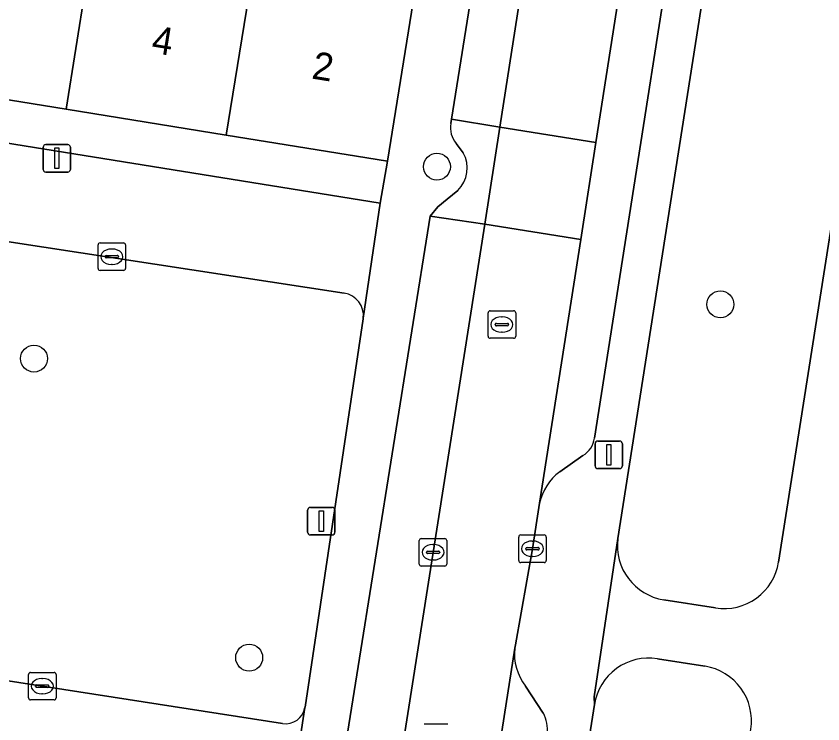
# Model space of a CAD drawing. Extents: x 163008 to 163854, y 382777 to 383982.
# Drawn here: x 163253.69 to 163282.98, y 383111.73 to 383137.42 of the extents above; entities that cross this region are included whole.
import ezdxf

# ---------------------------------------------------------------- set-up
doc = ezdxf.new("R2010")
doc.units = 0
for name, color, linetype in [('IMGEO_Boom', 7, 'Continuous'), ('IMGEO_Erf', 7, 'Continuous'), ('IMGEO_Groenvoorziening', 7, 'Continuous'), ('IMGEO_Kolk', 7, 'Continuous'), ('IMGEO_Lichtmast', 7, 'Continuous'), ('IMGEO_Pand', 7, 'Continuous'), ('IMGEO_Pand_nummerreeks', 7, 'Continuous'), ('IMGEO_Parkeervlak_open', 7, 'Continuous'), ('IMGEO_Rijbaan_lokaal_open', 7, 'Continuous'), ('IMGEO_Rioolput', 7, 'Continuous'), ('IMGEO_Verkeersbordpaal', 7, 'Continuous'), ('IMGEO_Voetpad_open', 7, 'Continuous')]:
    doc.layers.add(name, color=color, linetype=linetype)

msp = doc.modelspace()

# ---------------------------------------------------------------- linework, layer by layer
at = {"layer": 'IMGEO_Boom'}
for centre in [(163268.964, 383131.957), (163279.255, 383126.958), (163254.337, 383124.992), (163262.149, 383114.131)]:
    msp.add_circle(centre, 0.489, dxfattribs=at)
at = {"layer": 'IMGEO_Erf'}
msp.add_lwpolyline([(163255.5, 383134.044), (163249.739, 383134.974), (163243.979, 383135.904), (163238.071, 383136.858), (163237.896, 383135.882), (163237.819, 383135.321), (163266.909, 383130.633), (163267.168, 383132.16), (163261.316, 383133.105)], close=True, dxfattribs=at)
at = {"layer": 'IMGEO_Groenvoorziening'}
for points in [[(163285.801, 383145.855), (163279.973, 383146.774), (163275.529, 383118.456)], [(163281.366, 383117.602), (163285.801, 383145.855)], [(163265.602, 383127.364), (163239.589, 383131.347), (163239.155, 383130.7), (163236.864, 383116.463)], [(163264.173, 383112.32), (163264.176, 383112.34), (163266.288, 383126.43), (163266.291, 383126.455)], [(163277.202, 383116.233), (163279.079, 383115.937)], [(163237.36, 383115.781), (163263.363, 383111.743)], [(163278.696, 383113.82), (163276.967, 383114.093)], [(163274.68, 383112.429), (163270.193, 383083.981), (163275.873, 383083.085), (163280.36, 383111.533)]]:
    msp.add_lwpolyline(points, dxfattribs=at)
for centre, radius, start, end in [((163265.473, 383126.551), 0.823, 353.3139, 81.0086), ((163277.514, 383118.208), 2, 172.8902, 261.0391), ((163279.391, 383117.912), 1.999, 261.0219, 351.0895), ((163276.655, 383112.118), 1.999, 81.025, 171.0536), ((163278.387, 383111.846), 1.998, 350.9843, 81.0943), ((163263.472, 383112.447), 0.712, 261.1914, 349.7366)]:
    msp.add_arc(centre, radius, start, end, dxfattribs=at)
at = {"layer": 'IMGEO_Kolk'}
for p, q in [((163256.661, 383128.263), (163256.661, 383129.115)), ((163256.736, 383129.189), (163257.588, 383129.189)), ((163257.662, 383129.115), (163257.662, 383128.263)), ((163257.149, 383128.969), (163257.174, 383128.969)), ((163256.92, 383128.683), (163256.92, 383128.695)), ((163257.358, 383128.646), (163256.96, 383128.646)), ((163256.963, 383128.732), (163257.361, 383128.732)), ((163257.404, 383128.695), (163257.404, 383128.683)), ((163257.172, 383128.409), (163257.147, 383128.409)), ((163257.588, 383128.189), (163256.736, 383128.189)), ((163272.008, 383118.586), (163272.86, 383118.586)), ((163268.323, 383117.532), (163268.323, 383118.384)), ((163268.398, 383118.458), (163269.25, 383118.458)), ((163269.324, 383118.384), (163269.324, 383117.532)), ((163271.933, 383117.66), (163271.933, 383118.512)), ((163272.421, 383118.366), (163272.446, 383118.366)), ((163272.934, 383118.512), (163272.934, 383117.66)), ((163268.625, 383118.001), (163269.023, 383118.001)), ((163268.811, 383118.238), (163268.836, 383118.238)), ((163272.192, 383118.08), (163272.192, 383118.092)), ((163272.63, 383118.043), (163272.232, 383118.043)), ((163272.235, 383118.129), (163272.633, 383118.129)), ((163272.676, 383118.092), (163272.676, 383118.08)), ((163268.582, 383117.952), (163268.582, 383117.964)), ((163269.02, 383117.915), (163268.622, 383117.915)), ((163269.066, 383117.964), (163269.066, 383117.952)), ((163272.444, 383117.806), (163272.419, 383117.806)), ((163269.25, 383117.458), (163268.398, 383117.458)), ((163268.834, 383117.678), (163268.809, 383117.678)), ((163272.86, 383117.586), (163272.008, 383117.586)), ((163254.214, 383113.597), (163255.066, 383113.597)), ((163254.139, 383112.671), (163254.139, 383113.523)), ((163254.627, 383113.377), (163254.652, 383113.377)), ((163255.14, 383113.523), (163255.14, 383112.671)), ((163254.398, 383113.091), (163254.398, 383113.103)), ((163254.836, 383113.054), (163254.438, 383113.054)), ((163254.441, 383113.14), (163254.839, 383113.14)), ((163254.882, 383113.103), (163254.882, 383113.091)), ((163254.65, 383112.817), (163254.625, 383112.817)), ((163255.066, 383112.597), (163254.214, 383112.597))]:
    msp.add_line(p, q, dxfattribs=at)
for points in [[(163256.661, 383128.263), (163256.661, 383129.115)], [(163256.736, 383129.189), (163257.588, 383129.189)], [(163257.662, 383129.115), (163257.662, 383128.263)], [(163257.588, 383128.189), (163256.736, 383128.189)], [(163272.008, 383118.586), (163272.86, 383118.586)], [(163268.323, 383117.532), (163268.323, 383118.384)], [(163268.398, 383118.458), (163269.25, 383118.458)], [(163269.324, 383118.384), (163269.324, 383117.532)], [(163271.933, 383117.66), (163271.933, 383118.512)], [(163272.934, 383118.512), (163272.934, 383117.66)], [(163269.25, 383117.458), (163268.398, 383117.458)], [(163272.86, 383117.586), (163272.008, 383117.586)], [(163254.214, 383113.597), (163255.066, 383113.597)], [(163254.139, 383112.671), (163254.139, 383113.523)], [(163255.14, 383113.523), (163255.14, 383112.671)], [(163255.066, 383112.597), (163254.214, 383112.597)]]:
    msp.add_lwpolyline(points, dxfattribs=at)
for centre, radius, start, end in [((163256.738, 383129.113), 0.0765, 91.552, 178.448), ((163256.738, 383129.113), 0.0765, 91.552, 178.448), ((163257.586, 383129.113), 0.0765, 1.552, 88.448), ((163257.586, 383129.113), 0.0765, 1.552, 88.448), ((163256.96, 383128.692), 0.0403, 85.8775, 175.7526), ((163256.957, 383128.682), 0.0366, 178.938, 274.7102), ((163257.361, 383128.689), 0.043, 264.8664, 352.4533), ((163257.365, 383128.694), 0.0386, 1.7309, 96.639), ((163256.738, 383128.265), 0.0765, 181.552, 268.448), ((163256.738, 383128.265), 0.0765, 181.552, 268.448), ((163257.586, 383128.265), 0.0765, 271.552, 358.448), ((163257.586, 383128.265), 0.0765, 271.552, 358.448), ((163272.01, 383118.51), 0.0765, 91.552, 178.448), ((163272.01, 383118.51), 0.0765, 91.552, 178.448), ((163272.858, 383118.51), 0.0765, 1.552, 88.448), ((163272.858, 383118.51), 0.0765, 1.552, 88.448), ((163268.4, 383118.382), 0.0765, 91.552, 178.448), ((163268.4, 383118.382), 0.0765, 91.552, 178.448), ((163269.248, 383118.382), 0.0765, 1.552, 88.448), ((163269.248, 383118.382), 0.0765, 1.552, 88.448), ((163268.622, 383117.961), 0.0403, 85.8775, 175.7526), ((163269.027, 383117.963), 0.0386, 1.7309, 96.639), ((163272.232, 383118.089), 0.0403, 85.8775, 175.7526), ((163272.229, 383118.079), 0.0366, 178.938, 274.7102), ((163272.633, 383118.086), 0.043, 264.8664, 352.4533), ((163272.637, 383118.091), 0.0386, 1.7309, 96.639), ((163268.619, 383117.951), 0.0366, 178.938, 274.7102), ((163269.023, 383117.958), 0.043, 264.8664, 352.4533), ((163268.4, 383117.534), 0.0765, 181.552, 268.448), ((163268.4, 383117.534), 0.0765, 181.552, 268.448), ((163269.248, 383117.534), 0.0765, 271.552, 358.448), ((163269.248, 383117.534), 0.0765, 271.552, 358.448), ((163272.01, 383117.662), 0.0765, 181.552, 268.448), ((163272.01, 383117.662), 0.0765, 181.552, 268.448), ((163272.858, 383117.662), 0.0765, 271.552, 358.448), ((163272.858, 383117.662), 0.0765, 271.552, 358.448), ((163254.216, 383113.521), 0.0765, 91.552, 178.448), ((163254.216, 383113.521), 0.0765, 91.552, 178.448), ((163255.064, 383113.521), 0.0765, 1.552, 88.448), ((163255.064, 383113.521), 0.0765, 1.552, 88.448), ((163254.438, 383113.1), 0.0403, 85.8775, 175.7526), ((163254.435, 383113.09), 0.0366, 178.938, 274.7102), ((163254.839, 383113.097), 0.043, 264.8664, 352.4533), ((163254.843, 383113.102), 0.0386, 1.7309, 96.639), ((163254.216, 383112.673), 0.0765, 181.552, 268.448), ((163254.216, 383112.673), 0.0765, 181.552, 268.448), ((163255.064, 383112.673), 0.0765, 271.552, 358.448), ((163255.064, 383112.673), 0.0765, 271.552, 358.448)]:
    msp.add_arc(centre, radius, start, end, dxfattribs=at)
for centre, major_axis, ratio, start_param, end_param in [((163257.148, 383128.689), (-0.387, 0.002), 0.722429, 4.712389, 7.853982), ((163257.173, 383128.689), (-0.39, 0.002), 0.717154, 1.570796, 4.712389), ((163272.42, 383118.086), (-0.387, 0.002), 0.722429, 4.712389, 7.853982), ((163272.445, 383118.086), (-0.39, 0.002), 0.717154, 1.570796, 4.712389), ((163268.81, 383117.958), (-0.387, 0.002), 0.722429, 4.712389, 7.853982), ((163268.835, 383117.958), (-0.39, 0.002), 0.717154, 1.570796, 4.712389), ((163254.626, 383113.097), (-0.387, 0.002), 0.722429, 4.712389, 7.853982), ((163254.651, 383113.097), (-0.39, 0.002), 0.717154, 1.570796, 4.712389)]:
    msp.add_ellipse(centre, major_axis=major_axis, ratio=ratio, start_param=start_param, end_param=end_param, dxfattribs=at)
at = {"layer": 'IMGEO_Lichtmast'}
for p, q in [((163254.67, 383131.861), (163254.67, 383132.661)), ((163254.67, 383132.661), (163254.67, 383131.861)), ((163254.77, 383132.761), (163255.56, 383132.761)), ((163255.56, 383132.761), (163254.77, 383132.761)), ((163255.66, 383132.661), (163255.66, 383131.861)), ((163255.66, 383131.861), (163255.66, 383132.661)), ((163255.56, 383131.761), (163254.77, 383131.761)), ((163254.77, 383131.761), (163255.56, 383131.761)), ((163274.707, 383121.097), (163274.707, 383121.897)), ((163274.707, 383121.897), (163274.707, 383121.097)), ((163274.807, 383121.997), (163275.597, 383121.997)), ((163275.597, 383121.997), (163274.807, 383121.997)), ((163275.697, 383121.897), (163275.697, 383121.097)), ((163275.697, 383121.097), (163275.697, 383121.897)), ((163275.597, 383120.997), (163274.807, 383120.997)), ((163274.807, 383120.997), (163275.597, 383120.997))]:
    msp.add_line(p, q, dxfattribs=at)
for points in [[(163255.09, 383132.636), (163255.24, 383132.636), (163255.24, 383131.886), (163255.09, 383131.886), (163255.09, 383132.636)], [(163275.127, 383121.872), (163275.277, 383121.872), (163275.277, 383121.122), (163275.127, 383121.122), (163275.127, 383121.872)]]:
    msp.add_lwpolyline(points, dxfattribs=at)
for centre, start, end in [((163254.77, 383132.661), 90, 180), ((163254.77, 383132.661), 90, 180), ((163255.56, 383132.661), 0, 90), ((163255.56, 383132.661), 360, 90), ((163254.77, 383131.861), 180, 270), ((163254.77, 383131.861), 180, 270), ((163255.56, 383131.861), 270, 0), ((163255.56, 383131.861), 270, 0), ((163274.807, 383121.897), 90, 180), ((163274.807, 383121.897), 90, 180), ((163275.597, 383121.897), 0, 90), ((163275.597, 383121.897), 360, 90), ((163274.807, 383121.097), 180, 270), ((163274.807, 383121.097), 180, 270), ((163275.597, 383121.097), 270, 0), ((163275.597, 383121.097), 270, 0)]:
    msp.add_arc(centre, 0.1, start, end, dxfattribs=at)
at = {"layer": 'IMGEO_Pand'}
for points in [[(163263.102, 383144.124), (163263.872, 383148.876), (163260.267, 383149.442), (163258.74, 383149.682), (163257.974, 383144.953), (163257.264, 383145.068), (163255.5, 383134.044), (163261.316, 383133.105)], [(163255.5, 383134.044), (163257.264, 383145.068), (163251.522, 383145.997), (163251.032, 383142.951), (163249.739, 383134.974)], [(163263.102, 383144.124), (163261.316, 383133.105), (163267.168, 383132.16), (163268.457, 383140.137), (163264.805, 383140.728), (163265.297, 383143.769)]]:
    msp.add_lwpolyline(points, close=True, dxfattribs=at)
at = {"layer": 'IMGEO_Parkeervlak_open'}
for points in [[(163271.119, 383143.834), (163269.499, 383133.678), (163271.253, 383133.395), (163280.323, 383191.611), (163278.747, 383191.863), (163278.555, 383191.425), (163275.791, 383174.012)], [(163281.778, 383177.835), (163274.739, 383132.832), (163274.214, 383129.473), (163274.189, 383129.31), (163272.691, 383119.736)], [(163274.685, 383122.106), (163282.934, 383174.782)], [(163271.253, 383133.395), (163269.499, 383133.678), (163269.474, 383133.523)], [(163269.726, 383131.09), (163269.338, 383130.782), (163268.993, 383130.505), (163268.723, 383130.163), (163270.7, 383129.875), (163271.253, 383133.395)], [(163269.663, 383132.805), (163269.919, 383132.457)], [(163270.7, 383129.875), (163268.723, 383130.163), (163262.069, 383088.528), (163262.063, 383088.302), (163262.115, 383088.172), (163262.782, 383087.359)], [(163259.821, 383060.729), (163270.7, 383129.875)], [(163273.421, 383120.876), (163274.266, 383121.47)], [(163271.794, 383114.476), (163263.513, 383061.443)], [(163272.827, 383112.118), (163272.186, 383113.101)]]:
    msp.add_lwpolyline(points, dxfattribs=at)
for centre, radius, start, end in [((163270.298, 383133.356), 0.841, 168.5587, 220.9363), ((163268.934, 383131.899), 1.132, 314.398, 29.5296), ((163273.822, 383122.218), 0.87, 300.6605, 352.5853), ((163274.552, 383119.348), 1.901, 126.5125, 168.2205), ((163273.609, 383114.25), 1.829, 172.9095, 218.9152), ((163271.635, 383111.501), 1.343, 354.4526, 27.3696)]:
    msp.add_arc(centre, radius, start, end, dxfattribs=at)
at = {"layer": 'IMGEO_Rijbaan_lokaal_open'}
for points in [[(163280.323, 383191.611), (163271.253, 383133.395), (163274.739, 383132.832), (163281.778, 383177.835), (163281.931, 383179.059), (163282.521, 383182.549), (163283.842, 383191.049)], [(163274.739, 383132.832), (163271.253, 383133.395), (163270.7, 383129.875), (163274.189, 383129.31), (163274.214, 383129.473)]]:
    msp.add_lwpolyline(points, close=True, dxfattribs=at)
msp.add_lwpolyline([(163262.832, 383057.207), (163263.513, 383061.443), (163271.794, 383114.476), (163271.812, 383114.593), (163272.433, 383118.086), (163272.691, 383119.736), (163274.189, 383129.31), (163270.7, 383129.875), (163259.821, 383060.729), (163259.673, 383059.48), (163258.688, 383053.576), (163262.311, 383052.831)], dxfattribs=at)
at = {"layer": 'IMGEO_Rioolput'}
for p, q in [((163270.823, 383125.8), (163270.823, 383126.652)), ((163270.898, 383126.726), (163271.75, 383126.726)), ((163271.311, 383126.506), (163271.336, 383126.506)), ((163271.824, 383126.652), (163271.824, 383125.8)), ((163271.082, 383126.22), (163271.082, 383126.232)), ((163271.52, 383126.183), (163271.122, 383126.183)), ((163271.125, 383126.269), (163271.523, 383126.269)), ((163271.566, 383126.232), (163271.566, 383126.22)), ((163271.334, 383125.946), (163271.309, 383125.946)), ((163271.75, 383125.726), (163270.898, 383125.726)), ((163268.506, 383111.728), (163269.358, 383111.728))]:
    msp.add_line(p, q, dxfattribs=at)
for points in [[(163270.823, 383125.8), (163270.823, 383126.652)], [(163270.898, 383126.726), (163271.75, 383126.726)], [(163271.824, 383126.652), (163271.824, 383125.8)], [(163271.75, 383125.726), (163270.898, 383125.726)], [(163268.506, 383111.728), (163269.358, 383111.728)]]:
    msp.add_lwpolyline(points, dxfattribs=at)
for centre, radius, start, end in [((163270.9, 383126.65), 0.0765, 91.552, 178.448), ((163270.9, 383126.65), 0.0765, 91.552, 178.448), ((163271.748, 383126.65), 0.0765, 1.552, 88.448), ((163271.748, 383126.65), 0.0765, 1.552, 88.448), ((163271.122, 383126.229), 0.0403, 85.8775, 175.7526), ((163271.119, 383126.219), 0.0366, 178.938, 274.7102), ((163271.523, 383126.226), 0.043, 264.8664, 352.4533), ((163271.527, 383126.231), 0.0386, 1.7309, 96.639), ((163270.9, 383125.802), 0.0765, 181.552, 268.448), ((163270.9, 383125.802), 0.0765, 181.552, 268.448), ((163271.748, 383125.802), 0.0765, 271.552, 358.448), ((163271.748, 383125.802), 0.0765, 271.552, 358.448)]:
    msp.add_arc(centre, radius, start, end, dxfattribs=at)
for centre, major_axis, ratio, start_param, end_param in [((163271.31, 383126.226), (-0.387, 0.002), 0.722429, 4.712389, 7.853982), ((163271.335, 383126.226), (-0.39, 0.002), 0.717154, 1.570796, 4.712389)]:
    msp.add_ellipse(centre, major_axis=major_axis, ratio=ratio, start_param=start_param, end_param=end_param, dxfattribs=at)
at = {"layer": 'IMGEO_Verkeersbordpaal'}
for p, q in [((163264.271, 383118.686), (163264.271, 383119.486)), ((163264.271, 383119.486), (163264.271, 383118.686)), ((163264.371, 383119.586), (163265.161, 383119.586)), ((163265.161, 383119.586), (163264.371, 383119.586)), ((163265.261, 383119.486), (163265.261, 383118.686)), ((163265.261, 383118.686), (163265.261, 383119.486)), ((163265.161, 383118.586), (163264.371, 383118.586)), ((163264.371, 383118.586), (163265.161, 383118.586))]:
    msp.add_line(p, q, dxfattribs=at)
msp.add_lwpolyline([(163264.691, 383119.461), (163264.841, 383119.461), (163264.841, 383118.711), (163264.691, 383118.711), (163264.691, 383119.461)], dxfattribs=at)
for centre, start, end in [((163264.371, 383119.486), 90, 180), ((163264.371, 383119.486), 90, 180), ((163265.161, 383119.486), 0, 90), ((163265.161, 383119.486), 360, 90), ((163264.371, 383118.686), 180, 270), ((163264.371, 383118.686), 180, 270), ((163265.161, 383118.686), 270, 0), ((163265.161, 383118.686), 270, 0)]:
    msp.add_arc(centre, 0.1, start, end, dxfattribs=at)
at = {"layer": 'IMGEO_Voetpad_open'}
for points in [[(163265.57, 383054.888), (163269.985, 383082.335), (163275.662, 383081.422), (163275.873, 383083.085), (163270.193, 383083.981), (163274.68, 383112.429), (163274.673, 383112.705), (163275.529, 383118.456), (163279.973, 383146.774), (163285.801, 383145.855), (163286.065, 383147.534), (163280.237, 383148.453), (163284.671, 383176.706)], [(163290.5, 383175.79), (163286.065, 383147.534), (163285.801, 383145.855), (163281.366, 383117.602)], [(163282.934, 383174.782), (163274.685, 383122.106)], [(163271.991, 383163.012), (163270.324, 383152.219), (163270.282, 383151.95), (163270.099, 383150.762), (163268.457, 383140.137), (163267.168, 383132.16), (163266.909, 383130.633), (163266.291, 383126.455), (163266.288, 383126.43), (163264.176, 383112.34), (163264.173, 383112.32), (163263.52, 383108.014), (163263.279, 383106.473), (163261.93, 383097.996), (163261.735, 383098.027), (163259.619, 383084.866), (163259.384, 383083.403), (163257.275, 383070.289), (163255.991, 383062.434), (163254.811, 383055.03)], [(163269.474, 383133.523), (163269.499, 383133.678), (163271.119, 383143.834)], [(163266.291, 383126.455), (163266.909, 383130.633), (163237.819, 383135.321), (163237.896, 383135.882), (163236.759, 383136.055), (163236.517, 383136.095), (163233.783, 383117.895), (163233.769, 383117.799), (163233.721, 383117.514), (163232.95, 383112.902), (163234.063, 383112.721), (163234.432, 383112.662), (163263.52, 383108.014), (163264.173, 383112.32)], [(163269.919, 383132.457), (163269.663, 383132.805)], [(163236.864, 383116.463), (163239.155, 383130.7), (163239.589, 383131.347), (163265.602, 383127.364)], [(163262.782, 383087.359), (163262.115, 383088.172), (163262.063, 383088.302), (163262.069, 383088.528), (163268.723, 383130.163), (163268.993, 383130.505), (163269.338, 383130.782), (163269.726, 383131.09)], [(163274.266, 383121.47), (163273.421, 383120.876)], [(163272.691, 383119.736), (163272.433, 383118.086), (163271.812, 383114.593), (163271.794, 383114.476)], [(163275.529, 383118.456), (163274.673, 383112.705), (163274.68, 383112.429)], [(163279.079, 383115.937), (163277.202, 383116.233)], [(163263.363, 383111.743), (163237.36, 383115.781)], [(163276.967, 383114.093), (163278.696, 383113.82)], [(163272.186, 383113.101), (163272.827, 383112.118)]]:
    msp.add_lwpolyline(points, dxfattribs=at)
for centre, radius, start, end in [((163270.298, 383133.356), 0.841, 168.5587, 220.9363), ((163268.934, 383131.899), 1.132, 314.398, 29.5296), ((163265.473, 383126.551), 0.823, 353.3139, 81.0086), ((163273.822, 383122.218), 0.87, 300.6605, 352.5853), ((163274.552, 383119.348), 1.901, 126.5125, 168.2205), ((163277.514, 383118.208), 2, 172.8902, 261.0391), ((163279.391, 383117.912), 1.999, 261.0219, 351.0895), ((163273.609, 383114.25), 1.829, 172.9095, 218.9152), ((163276.655, 383112.118), 1.999, 81.025, 171.0536), ((163278.387, 383111.846), 1.998, 350.9843, 81.0943), ((163263.472, 383112.447), 0.712, 261.1914, 349.7366), ((163271.635, 383111.501), 1.343, 354.4526, 27.3696)]:
    msp.add_arc(centre, radius, start, end, dxfattribs=at)

# ---------------------------------------------------------------- texts
at = {"layer": 'IMGEO_Pand_nummerreeks'}
for s, rotation, p in [('4', 350.8269, (163258.569, 383136.101)), ('2', 350.8282, (163264.387, 383135.162))]:
    msp.add_text(s, height=1, rotation=rotation, dxfattribs=at).set_placement(p)

doc.saveas('drawing.dxf')
